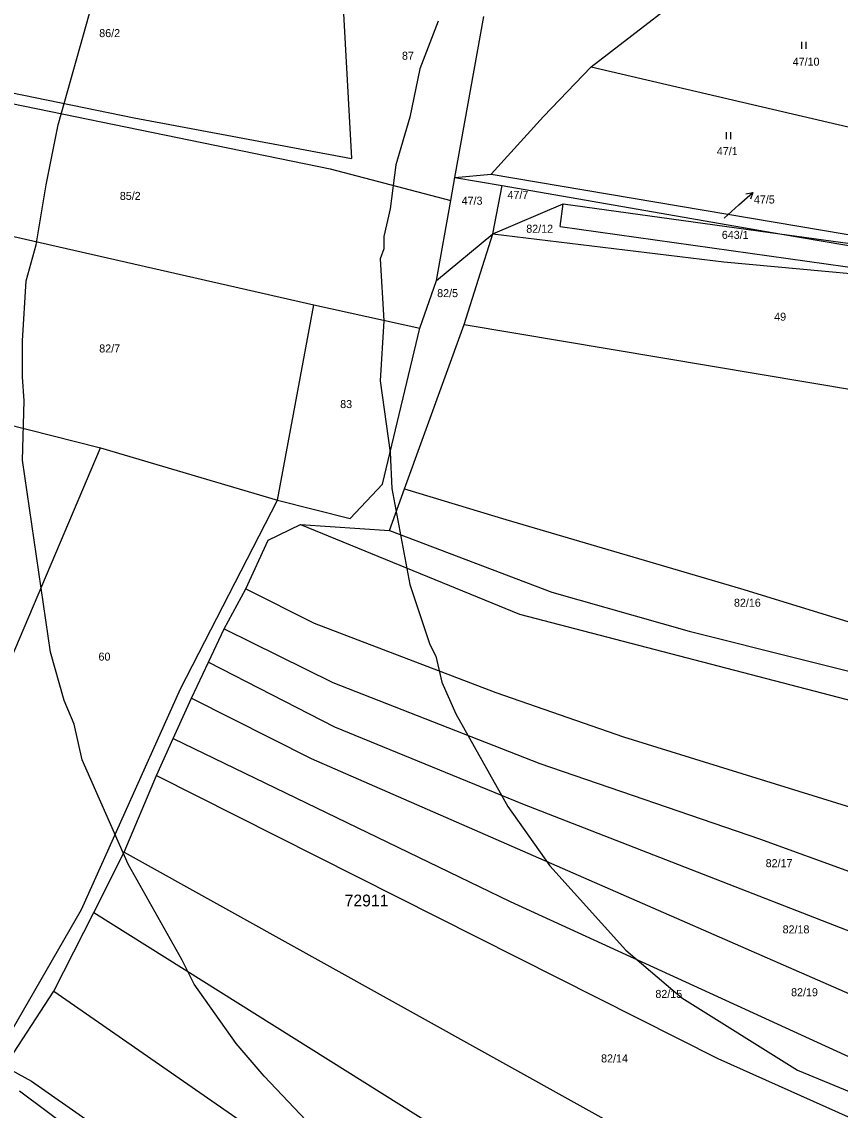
# Model space of a CAD drawing. Extents: x -743888 to -742027, y -1128394 to -1126768.
# Drawn here: x -743261.6 to -743087.8, y -1127556.1 to -1127325 of the extents above; entities that cross this region are included whole.
import ezdxf

# ---------------------------------------------------------------- set-up
doc = ezdxf.new("R2010")
doc.units = 0
for name, color, linetype in [('Vrstva 1', 7, 'Continuous'), ('Vrstva 16', 7, 'Continuous'), ('Vrstva 18', 7, 'Continuous'), ('Vrstva 25', 7, 'Continuous'), ('Vrstva 52', 7, 'Continuous'), ('Vrstva 53', 7, 'Continuous'), ('Vrstva 6', 7, 'Continuous')]:
    doc.layers.add(name, color=color, linetype=linetype)

msp = doc.modelspace()

# ---------------------------------------------------------------- linework, layer by layer
at = {"layer": 'Vrstva 1'}
for points in [[(-743169.65, -1127358.07), (-743163.52, -1127323.93)], [(-743170.53, -1127362.98), (-743169.65, -1127358.07)], [(-743173.59, -1127379.99), (-743170.53, -1127362.98)], [(-743161.61, -1127370.05), (-743146.67, -1127363.71)], [(-743147.34, -1127368.46), (-743146.67, -1127363.71)], [(-743146.67, -1127363.71), (-743100.68, -1127370.05)], [(-743173.59, -1127379.99), (-743161.61, -1127370.05)], [(-743147.34, -1127368.46), (-743054.48, -1127381.54)], [(-743100.68, -1127370.05), (-743028.55, -1127379.99)], [(-743265.25, -1127546.83), (-743259.6, -1127550)], [(-743259.6, -1127550), (-743235.8, -1127566.59)]]:
    msp.add_lwpolyline(points, dxfattribs=at)
at = {"layer": 'Vrstva 16'}
msp.add_line((-743107.9, -1127361.55), (-743106.43, -1127361.24), dxfattribs=at)
for points in [[(-743109.4, -1127363.92), (-743106.43, -1127361.24), (-743106.89, -1127362.67)], [(-743112.48, -1127366.7), (-743109.4, -1127363.92)]]:
    msp.add_lwpolyline(points, dxfattribs=at)
at = {"layer": 'Vrstva 25'}
for p, q in [((-743096.06, -1127329.29), (-743096.06, -1127330.79)), ((-743095.06, -1127330.79), (-743095.06, -1127329.29)), ((-743112.07, -1127348.48), (-743112.07, -1127349.98)), ((-743111.07, -1127349.98), (-743111.07, -1127348.48))]:
    msp.add_line(p, q, dxfattribs=at)
at = {"layer": 'Vrstva 52'}
for points in [[(-743197.44, -1127562.38), (-743210.19, -1127548.88), (-743216.13, -1127542), (-743225.06, -1127529.38), (-743227.56, -1127524.25), (-743239.06, -1127503.88), (-743248.81, -1127481.75), (-743250.5, -1127474.13), (-743252.63, -1127469.13), (-743255.56, -1127458.88), (-743261.5, -1127418.13), (-743261.13, -1127405.5), (-743261.5, -1127400.38), (-743261.5, -1127392.75), (-743260.69, -1127380), (-743258.56, -1127372.38), (-743256.44, -1127359.63), (-743253.88, -1127346.88), (-743245.38, -1127316.38)], [(-743173.25, -1127324.88), (-743177.13, -1127335), (-743179.25, -1127345.25), (-743182.19, -1127355.38), (-743183.44, -1127364.75), (-743184.75, -1127370.63), (-743184.75, -1127373.25), (-743185.56, -1127375.38), (-743184.75, -1127388.5), (-743185.56, -1127401.25), (-743183.44, -1127416.5), (-743183.06, -1127424.13), (-743179.25, -1127444.5), (-743175, -1127457.25), (-743173.69, -1127459.75), (-743172.44, -1127465.25), (-743169.44, -1127472), (-743158.44, -1127491.63), (-743149.5, -1127504.25), (-743133.38, -1127522.13), (-743121.5, -1127532.25), (-743096.94, -1127547.63), (-743060, -1127562.88)]]:
    msp.add_lwpolyline(points, dxfattribs=at)
at = {"layer": 'Vrstva 6'}
for points in [[(-743140.7, -1127334.62), (-743113.92, -1127313.85)], [(-743193.71, -1127316.81), (-743191.59, -1127354.07)], [(-743295.73, -1127333.53), (-743237.76, -1127345.4)], [(-743150.85, -1127345.11), (-743140.7, -1127334.62)], [(-743140.7, -1127334.62), (-743063.68, -1127352.59)], [(-743296.23, -1127335.74), (-743196.16, -1127356.25)], [(-743237.76, -1127345.4), (-743191.59, -1127354.07)], [(-743161.95, -1127357.36), (-743150.85, -1127345.11)], [(-743196.16, -1127356.25), (-743170.53, -1127362.98)], [(-743169.65, -1127358.07), (-743161.95, -1127357.36)], [(-743169.65, -1127358.07), (-743159.66, -1127359.81)], [(-743161.95, -1127357.36), (-743066.9, -1127373.47)], [(-743161.61, -1127370.05), (-743159.66, -1127359.81)], [(-743159.66, -1127359.81), (-743100.68, -1127370.05)], [(-743167.67, -1127389.27), (-743161.61, -1127370.05)], [(-743161.61, -1127370.05), (-743112.56, -1127376.02)], [(-743100.68, -1127370.05), (-743028.35, -1127382.31)], [(-743264.92, -1127370.24), (-743199.65, -1127385.13)], [(-743112.56, -1127376.02), (-743063.36, -1127380.56)], [(-743177.11, -1127390.05), (-743173.59, -1127379.99)], [(-743207.37, -1127426.59), (-743199.65, -1127385.13)], [(-743199.65, -1127385.13), (-743177.11, -1127390.05)], [(-743185.02, -1127423.21), (-743177.11, -1127390.05)], [(-743180.36, -1127424.17), (-743167.67, -1127389.27)], [(-743167.67, -1127389.27), (-743084.2, -1127403.32)], [(-743275.71, -1127407.69), (-743244.94, -1127415.47)], [(-743264.86, -1127462.59), (-743244.94, -1127415.47)], [(-743244.94, -1127415.47), (-743207.37, -1127426.59)], [(-743191.91, -1127430.5), (-743185.02, -1127423.21)], [(-743183.58, -1127433.05), (-743180.36, -1127424.17)], [(-743180.36, -1127424.17), (-743158.88, -1127430.74)], [(-743227.96, -1127466.68), (-743207.37, -1127426.59)], [(-743207.37, -1127426.59), (-743191.91, -1127430.5)], [(-743209.32, -1127435.1), (-743202.45, -1127431.75)], [(-743202.45, -1127431.75), (-743183.58, -1127433.05)], [(-743202.45, -1127431.75), (-743155.92, -1127450.8)], [(-743158.88, -1127430.74), (-743108.99, -1127445.38)], [(-743183.58, -1127433.05), (-743149.11, -1127446.12)], [(-743214.09, -1127445.46), (-743209.32, -1127435.1)], [(-743218.68, -1127453.92), (-743214.09, -1127445.46)], [(-743214.09, -1127445.46), (-743199.57, -1127452.71)], [(-743149.11, -1127446.12), (-743119.92, -1127454.41)], [(-743108.99, -1127445.38), (-743041.59, -1127466.09)], [(-743155.92, -1127450.8), (-743071.4, -1127472.85)], [(-743199.57, -1127452.71), (-743160.99, -1127467.42)], [(-743221.96, -1127460.98), (-743218.68, -1127453.92)], [(-743218.68, -1127453.92), (-743195.56, -1127465.33)], [(-743119.92, -1127454.41), (-743047.66, -1127472.53)], [(-743225.6, -1127468.62), (-743221.96, -1127460.98)], [(-743221.96, -1127460.98), (-743195.25, -1127474.76)], [(-743248.98, -1127513.51), (-743227.96, -1127466.68)], [(-743195.56, -1127465.33), (-743151.66, -1127482.51)], [(-743229.49, -1127477.19), (-743225.6, -1127468.62)], [(-743225.6, -1127468.62), (-743200.19, -1127481.49)], [(-743160.99, -1127467.42), (-743133.85, -1127476.88)], [(-743195.25, -1127474.76), (-743155.28, -1127491.09)], [(-743233.06, -1127485.07), (-743229.49, -1127477.19)], [(-743229.49, -1127477.19), (-743157.93, -1127511.82)], [(-743133.85, -1127476.88), (-743056.44, -1127500.82)], [(-743200.19, -1127481.49), (-743164.36, -1127497.11)], [(-743151.66, -1127482.51), (-743104.96, -1127498.48)], [(-743239.89, -1127501.37), (-743233.06, -1127485.07)], [(-743233.06, -1127485.07), (-743113.85, -1127545.15)], [(-743155.28, -1127491.09), (-743049.5, -1127532.27)], [(-743164.36, -1127497.11), (-743055.93, -1127544.5)], [(-743104.96, -1127498.48), (-743045.31, -1127520.19)], [(-743246.36, -1127514.17), (-743239.89, -1127501.37)], [(-743239.89, -1127501.37), (-743082.43, -1127588.87)], [(-743157.93, -1127511.82), (-743062.27, -1127555.66)], [(-743267.48, -1127545.58), (-743248.98, -1127513.51)], [(-743254.82, -1127530.84), (-743246.36, -1127514.17)], [(-743246.36, -1127514.17), (-743127.6, -1127588.59)], [(-743265.25, -1127546.83), (-743254.82, -1127530.84)], [(-743254.82, -1127530.84), (-743140.32, -1127610.37)], [(-743113.85, -1127545.15), (-743067.95, -1127565.66)], [(-743262.15, -1127552), (-743250.66, -1127560.62)]]:
    msp.add_lwpolyline(points, dxfattribs=at)

# ---------------------------------------------------------------- texts
at = {"layer": 'Vrstva 16'}
msp.add_text('47/5', height=1.7, dxfattribs=at).set_placement((-743106.17, -1127363.61))
at = {"layer": 'Vrstva 18'}
for s, height, p in [('86/2', 1.7, (-743245.19, -1127328.28)), ('87', 1.7, (-743180.9, -1127333.09)), ('47/10', 1.7, (-743097.93, -1127334.35)), ('47/1', 1.7, (-743114.04, -1127353.34)), ('47/7', 1.7, (-743158.5, -1127362.63)), ('85/2', 1.7, (-743240.82, -1127362.85)), ('47/3', 1.7, (-743168.23, -1127363.87)), ('47/5', 0.1, (-743112.48, -1127366.7)), ('82/12', 1.7, (-743154.51, -1127369.82)), ('643/1', 1.7, (-743112.98, -1127371.12)), ('82/5', 1.7, (-743173.43, -1127383.49)), ('49', 1.7, (-743101.86, -1127388.5)), ('82/7', 1.7, (-743245.19, -1127395.24)), ('83', 1.7, (-743194.02, -1127407.05)), ('82/16', 1.7, (-743110.4, -1127449.23)), ('60', 1.7, (-743245.35, -1127460.67)), ('82/17', 1.7, (-743103.67, -1127504.53)), ('82/18', 1.7, (-743100.07, -1127518.59)), ('82/15', 1.7, (-743127.09, -1127532.29)), ('82/19', 1.7, (-743098.27, -1127531.93)), ('82/14', 1.7, (-743138.62, -1127545.99))]:
    msp.add_text(s, height=height, dxfattribs=at).set_placement(p)
at = {"layer": 'Vrstva 53'}
msp.add_text('72911', height=2.5, dxfattribs=at).set_placement((-743193.08, -1127512.86))

doc.saveas('drawing.dxf')
